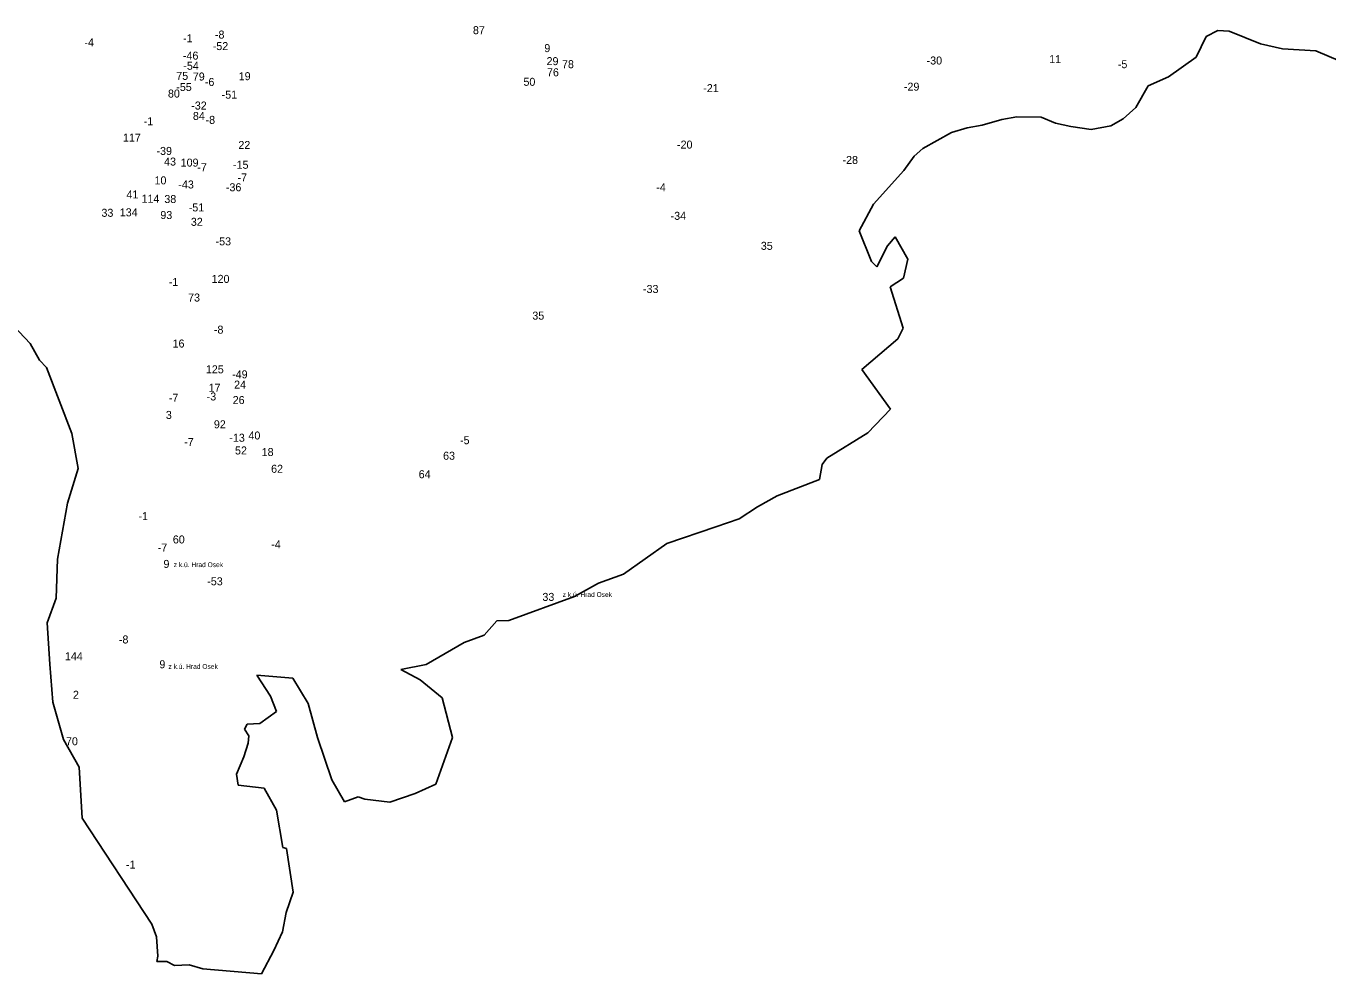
# Model space of a CAD drawing. Extents: x -790709 to -785360, y -974907 to -970918.
# Drawn here: x -788603 to -786976, y -974907 to -973723 of the extents above; entities that cross this region are included whole.
import ezdxf

# ---------------------------------------------------------------- set-up
doc = ezdxf.new("R2010")
doc.units = 0
for name, color, linetype in [('Vrstva 13', 7, 'Continuous'), ('Vrstva 15', 7, 'Continuous'), ('Vrstva 24', 7, 'Continuous'), ('Vrstva 63', 7, 'Continuous')]:
    doc.layers.add(name, color=color, linetype=linetype)

msp = doc.modelspace()

# ---------------------------------------------------------------- linework, layer by layer
at = {"layer": 'Vrstva 13'}
for p, q in [((-787127.9, -973736.1), (-787113.3, -973728.4)), ((-787127.9, -973736.1), (-787113.3, -973728.4)), ((-787127.9, -973736.1), (-787113.3, -973728.4)), ((-787113.3, -973728.4), (-787099.4, -973729.3)), ((-787113.3, -973728.4), (-787099.4, -973729.3)), ((-787113.3, -973728.4), (-787099.4, -973729.3)), ((-787140.6, -973762), (-787127.9, -973736.1)), ((-787140.6, -973762), (-787127.9, -973736.1)), ((-787140.6, -973762), (-787127.9, -973736.1)), ((-787099.4, -973729.3), (-787060.2, -973745.3)), ((-787099.4, -973729.3), (-787060.2, -973745.3)), ((-787099.4, -973729.3), (-787060.2, -973745.3)), ((-787060.2, -973745.3), (-787032.7, -973751.5)), ((-787060.2, -973745.3), (-787032.7, -973751.5)), ((-787060.2, -973745.3), (-787032.7, -973751.5)), ((-787032.7, -973751.5), (-786991, -973754)), ((-787032.7, -973751.5), (-786991, -973754)), ((-787032.7, -973751.5), (-786991, -973754)), ((-786991, -973754), (-786960.6, -973766.9)), ((-786991, -973754), (-786960.6, -973766.9)), ((-786991, -973754), (-786960.6, -973766.9)), ((-787175.1, -973786.5), (-787140.6, -973762)), ((-787175.1, -973786.5), (-787140.6, -973762)), ((-787175.1, -973786.5), (-787140.6, -973762)), ((-787200.5, -973797.6), (-787175.1, -973786.5)), ((-787200.5, -973797.6), (-787175.1, -973786.5)), ((-787200.5, -973797.6), (-787175.1, -973786.5)), ((-787216.1, -973824.8), (-787200.5, -973797.6)), ((-787216.1, -973824.8), (-787200.5, -973797.6)), ((-787216.1, -973824.8), (-787200.5, -973797.6)), ((-787231.7, -973838.8), (-787216.1, -973824.8)), ((-787231.7, -973838.8), (-787216.1, -973824.8)), ((-787231.7, -973838.8), (-787216.1, -973824.8)), ((-787407.8, -973846.9), (-787383.2, -973839.8)), ((-787407.8, -973846.9), (-787383.2, -973839.8)), ((-787407.8, -973846.9), (-787383.2, -973839.8)), ((-787383.2, -973839.8), (-787364.7, -973836.5)), ((-787383.2, -973839.8), (-787364.7, -973836.5)), ((-787383.2, -973839.8), (-787364.7, -973836.5)), ((-787364.7, -973836.5), (-787334.1, -973836.9)), ((-787364.7, -973836.5), (-787334.1, -973836.9)), ((-787364.7, -973836.5), (-787334.1, -973836.9)), ((-787334.1, -973836.9), (-787316.2, -973844.2)), ((-787334.1, -973836.9), (-787316.2, -973844.2)), ((-787334.1, -973836.9), (-787316.2, -973844.2)), ((-787247.1, -973847.5), (-787231.7, -973838.8)), ((-787247.1, -973847.5), (-787231.7, -973838.8)), ((-787247.1, -973847.5), (-787231.7, -973838.8)), ((-787482.1, -973876), (-787446.1, -973856.1)), ((-787482.1, -973876), (-787446.1, -973856.1)), ((-787482.1, -973876), (-787446.1, -973856.1)), ((-787446.1, -973856.1), (-787426.5, -973850)), ((-787446.1, -973856.1), (-787426.5, -973850)), ((-787446.1, -973856.1), (-787426.5, -973850)), ((-787426.5, -973850), (-787407.8, -973846.9)), ((-787426.5, -973850), (-787407.8, -973846.9)), ((-787426.5, -973850), (-787407.8, -973846.9)), ((-787316.2, -973844.2), (-787297.1, -973848.6)), ((-787316.2, -973844.2), (-787297.1, -973848.6)), ((-787316.2, -973844.2), (-787297.1, -973848.6)), ((-787297.1, -973848.6), (-787271.7, -973852.1)), ((-787297.1, -973848.6), (-787271.7, -973852.1)), ((-787297.1, -973848.6), (-787271.7, -973852.1)), ((-787271.7, -973852.1), (-787247.1, -973847.5)), ((-787271.7, -973852.1), (-787247.1, -973847.5)), ((-787271.7, -973852.1), (-787247.1, -973847.5)), ((-787505.8, -973903.5), (-787492.7, -973885.6)), ((-787505.8, -973903.5), (-787492.7, -973885.6)), ((-787505.8, -973903.5), (-787492.7, -973885.6)), ((-787492.7, -973885.6), (-787482.1, -973876)), ((-787492.7, -973885.6), (-787482.1, -973876)), ((-787492.7, -973885.6), (-787482.1, -973876)), ((-787543.7, -973945.4), (-787505.8, -973903.5)), ((-787543.7, -973945.4), (-787505.8, -973903.5)), ((-787543.7, -973945.4), (-787505.8, -973903.5)), ((-787561.8, -973978.7), (-787543.7, -973945.4)), ((-787561.8, -973978.7), (-787543.7, -973945.4)), ((-787561.8, -973978.7), (-787543.7, -973945.4)), ((-787546, -974017), (-787561.8, -973978.7)), ((-787546, -974017), (-787561.8, -973978.7)), ((-787546, -974017), (-787561.8, -973978.7)), ((-787516.5, -973986.2), (-787526.1, -973997.4)), ((-787516.5, -973986.2), (-787526.1, -973997.4)), ((-787516.5, -973986.2), (-787526.1, -973997.4)), ((-787500.7, -974014.1), (-787516.5, -973986.2)), ((-787500.7, -974014.1), (-787516.5, -973986.2)), ((-787500.7, -974014.1), (-787516.5, -973986.2)), ((-787526.1, -973997.4), (-787539.4, -974023.7)), ((-787526.1, -973997.4), (-787539.4, -974023.7)), ((-787526.1, -973997.4), (-787539.4, -974023.7)), ((-787539.4, -974023.7), (-787546, -974017)), ((-787539.4, -974023.7), (-787546, -974017)), ((-787539.4, -974023.7), (-787546, -974017)), ((-787506.1, -974038.2), (-787500.7, -974014.1)), ((-787506.1, -974038.2), (-787500.7, -974014.1)), ((-787506.1, -974038.2), (-787500.7, -974014.1)), ((-788660.2, -974053.6), (-788597.4, -974119.5)), ((-787522.8, -974048.7), (-787506.1, -974038.2)), ((-787522.8, -974048.7), (-787506.1, -974038.2)), ((-787522.8, -974048.7), (-787506.1, -974038.2)), ((-787506.6, -974100.3), (-787522.8, -974048.7)), ((-787506.6, -974100.3), (-787522.8, -974048.7)), ((-787506.6, -974100.3), (-787522.8, -974048.7)), ((-787513.2, -974114), (-787506.6, -974100.3)), ((-787513.2, -974114), (-787506.6, -974100.3)), ((-787513.2, -974114), (-787506.6, -974100.3)), ((-787558.2, -974152.3), (-787513.2, -974114)), ((-787558.2, -974152.3), (-787513.2, -974114)), ((-787558.2, -974152.3), (-787513.2, -974114)), ((-788597.4, -974119.5), (-788585.8, -974140.5)), ((-788585.8, -974140.5), (-788577.2, -974149.6)), ((-788577.2, -974149.6), (-788545.6, -974232.1)), ((-787522.6, -974201.9), (-787558.2, -974152.3)), ((-787522.6, -974201.9), (-787558.2, -974152.3)), ((-787522.6, -974201.9), (-787558.2, -974152.3)), ((-787550.6, -974231.4), (-787522.6, -974201.9)), ((-787550.6, -974231.4), (-787522.6, -974201.9)), ((-787550.6, -974231.4), (-787522.6, -974201.9)), ((-788545.6, -974232.1), (-788537.5, -974276)), ((-787601.8, -974263), (-787550.6, -974231.4)), ((-787601.8, -974263), (-787550.6, -974231.4)), ((-787601.8, -974263), (-787550.6, -974231.4)), ((-787607.8, -974270.8), (-787601.8, -974263)), ((-787607.8, -974270.8), (-787601.8, -974263)), ((-787607.8, -974270.8), (-787601.8, -974263)), ((-788537.5, -974276), (-788550.7, -974319.1)), ((-787611.1, -974289.5), (-787607.8, -974270.8)), ((-787611.1, -974289.5), (-787607.8, -974270.8)), ((-787611.1, -974289.5), (-787607.8, -974270.8)), ((-787664.2, -974310.2), (-787611.1, -974289.5)), ((-787664.2, -974310.2), (-787611.1, -974289.5)), ((-787664.2, -974310.2), (-787611.1, -974289.5)), ((-787688.7, -974323.7), (-787664.2, -974310.2)), ((-787688.7, -974323.7), (-787664.2, -974310.2)), ((-787688.7, -974323.7), (-787664.2, -974310.2)), ((-788550.7, -974319.1), (-788563.5, -974389.2)), ((-787711.6, -974338.6), (-787688.7, -974323.7)), ((-787711.6, -974338.6), (-787688.7, -974323.7)), ((-787711.6, -974338.6), (-787688.7, -974323.7)), ((-787740.6, -974348.6), (-787711.6, -974338.6)), ((-787740.6, -974348.6), (-787711.6, -974338.6)), ((-787740.6, -974348.6), (-787711.6, -974338.6)), ((-787802, -974369.7), (-787740.6, -974348.6)), ((-787802, -974369.7), (-787740.6, -974348.6)), ((-787802, -974369.7), (-787740.6, -974348.6)), ((-787855.9, -974407.8), (-787802, -974369.7)), ((-787855.9, -974407.8), (-787802, -974369.7)), ((-787855.9, -974407.8), (-787802, -974369.7)), ((-788563.5, -974389.2), (-788565, -974437.7)), ((-787887.3, -974419.3), (-787855.9, -974407.8)), ((-787887.3, -974419.3), (-787855.9, -974407.8)), ((-787887.3, -974419.3), (-787855.9, -974407.8)), ((-787917.1, -974435.9), (-787887.3, -974419.3)), ((-787917.1, -974435.9), (-787887.3, -974419.3)), ((-787917.1, -974435.9), (-787887.3, -974419.3)), ((-788565, -974437.7), (-788576.2, -974468.8)), ((-787999.3, -974465.7), (-787917.1, -974435.9)), ((-787999.3, -974465.7), (-787917.1, -974435.9)), ((-787999.3, -974465.7), (-787917.1, -974435.9)), ((-788576.2, -974468.8), (-788572.8, -974520.5)), ((-788030.1, -974484.2), (-788014.5, -974466.1)), ((-788030.1, -974484.2), (-788014.5, -974466.1)), ((-788030.1, -974484.2), (-788014.5, -974466.1)), ((-788014.5, -974466.1), (-787999.3, -974465.7)), ((-788014.5, -974466.1), (-787999.3, -974465.7)), ((-788014.5, -974466.1), (-787999.3, -974465.7)), ((-788102.7, -974520.9), (-788055.3, -974493.4)), ((-788102.7, -974520.9), (-788055.3, -974493.4)), ((-788102.7, -974520.9), (-788055.3, -974493.4)), ((-788055.3, -974493.4), (-788030.1, -974484.2)), ((-788055.3, -974493.4), (-788030.1, -974484.2)), ((-788055.3, -974493.4), (-788030.1, -974484.2)), ((-788572.8, -974520.5), (-788569.1, -974568)), ((-788134.2, -974527.1), (-788102.7, -974520.9)), ((-788134.2, -974527.1), (-788102.7, -974520.9)), ((-788134.2, -974527.1), (-788102.7, -974520.9)), ((-788297.1, -974560.4), (-788314.2, -974534)), ((-788314.2, -974534), (-788269.2, -974537.9)), ((-788297.1, -974560.4), (-788314.2, -974534)), ((-788314.2, -974534), (-788269.2, -974537.9)), ((-788297.1, -974560.4), (-788314.2, -974534)), ((-788314.2, -974534), (-788269.2, -974537.9)), ((-788269.2, -974537.9), (-788250.1, -974569.4)), ((-788269.2, -974537.9), (-788250.1, -974569.4)), ((-788269.2, -974537.9), (-788250.1, -974569.4)), ((-788110.2, -974539.8), (-788134.2, -974527.1)), ((-788110.2, -974539.8), (-788134.2, -974527.1)), ((-788110.2, -974539.8), (-788134.2, -974527.1)), ((-788082.5, -974562.3), (-788110.2, -974539.8)), ((-788082.5, -974562.3), (-788110.2, -974539.8)), ((-788082.5, -974562.3), (-788110.2, -974539.8)), ((-788569.1, -974568), (-788555.7, -974614.7)), ((-788289.8, -974579.4), (-788297.1, -974560.4)), ((-788289.8, -974579.4), (-788297.1, -974560.4)), ((-788289.8, -974579.4), (-788297.1, -974560.4)), ((-788250.1, -974569.4), (-788238.4, -974611.8)), ((-788250.1, -974569.4), (-788238.4, -974611.8)), ((-788250.1, -974569.4), (-788238.4, -974611.8)), ((-788069.8, -974612), (-788082.5, -974562.3)), ((-788069.8, -974612), (-788082.5, -974562.3)), ((-788069.8, -974612), (-788082.5, -974562.3)), ((-788310.6, -974594.4), (-788289.8, -974579.4)), ((-788310.6, -974594.4), (-788289.8, -974579.4)), ((-788310.6, -974594.4), (-788289.8, -974579.4)), ((-788329.6, -974601.4), (-788326.3, -974595.2)), ((-788329.6, -974601.4), (-788326.3, -974595.2)), ((-788329.6, -974601.4), (-788326.3, -974595.2)), ((-788324.4, -974610), (-788329.6, -974601.4)), ((-788324.4, -974610), (-788329.6, -974601.4)), ((-788324.4, -974610), (-788329.6, -974601.4)), ((-788326.3, -974595.2), (-788310.6, -974594.4)), ((-788326.3, -974595.2), (-788310.6, -974594.4)), ((-788326.3, -974595.2), (-788310.6, -974594.4)), ((-788555.7, -974614.7), (-788536.2, -974648.9)), ((-788330.6, -974636), (-788325.2, -974618.9)), ((-788330.6, -974636), (-788325.2, -974618.9)), ((-788330.6, -974636), (-788325.2, -974618.9)), ((-788325.2, -974618.9), (-788324.4, -974610)), ((-788325.2, -974618.9), (-788324.4, -974610)), ((-788325.2, -974618.9), (-788324.4, -974610)), ((-788238.4, -974611.8), (-788220.7, -974665.1)), ((-788238.4, -974611.8), (-788220.7, -974665.1)), ((-788238.4, -974611.8), (-788220.7, -974665.1)), ((-788090.7, -974670.3), (-788069.8, -974612)), ((-788090.7, -974670.3), (-788069.8, -974612)), ((-788090.7, -974670.3), (-788069.8, -974612)), ((-788339.8, -974657.9), (-788330.6, -974636)), ((-788339.8, -974657.9), (-788330.6, -974636)), ((-788339.8, -974657.9), (-788330.6, -974636)), ((-788536.2, -974648.9), (-788532.3, -974712.8)), ((-788337.7, -974671.4), (-788339.8, -974657.9)), ((-788337.7, -974671.4), (-788339.8, -974657.9)), ((-788337.7, -974671.4), (-788339.8, -974657.9)), ((-788305, -974675.3), (-788337.7, -974671.4)), ((-788305, -974675.3), (-788337.7, -974671.4)), ((-788305, -974675.3), (-788337.7, -974671.4)), ((-788220.7, -974665.1), (-788204.7, -974692.4)), ((-788220.7, -974665.1), (-788204.7, -974692.4)), ((-788220.7, -974665.1), (-788204.7, -974692.4)), ((-788116.3, -974682), (-788090.7, -974670.3)), ((-788116.3, -974682), (-788090.7, -974670.3)), ((-788116.3, -974682), (-788090.7, -974670.3)), ((-788289.6, -974702.8), (-788305, -974675.3)), ((-788289.6, -974702.8), (-788305, -974675.3)), ((-788289.6, -974702.8), (-788305, -974675.3)), ((-788204.7, -974692.4), (-788187.8, -974686.2)), ((-788204.7, -974692.4), (-788187.8, -974686.2)), ((-788204.7, -974692.4), (-788187.8, -974686.2)), ((-788187.8, -974686.2), (-788179.3, -974689.1)), ((-788187.8, -974686.2), (-788179.3, -974689.1)), ((-788187.8, -974686.2), (-788179.3, -974689.1)), ((-788148.1, -974692.6), (-788116.3, -974682)), ((-788148.1, -974692.6), (-788116.3, -974682)), ((-788148.1, -974692.6), (-788116.3, -974682)), ((-788281.7, -974749.5), (-788289.6, -974702.8)), ((-788281.7, -974749.5), (-788289.6, -974702.8)), ((-788281.7, -974749.5), (-788289.6, -974702.8)), ((-788179.3, -974689.1), (-788148.1, -974692.6)), ((-788179.3, -974689.1), (-788148.1, -974692.6)), ((-788179.3, -974689.1), (-788148.1, -974692.6)), ((-788532.3, -974712.8), (-788445.4, -974845.1)), ((-788277.1, -974750.7), (-788281.7, -974749.5)), ((-788277.1, -974750.7), (-788281.7, -974749.5)), ((-788277.1, -974750.7), (-788281.7, -974749.5)), ((-788269, -974805.3), (-788277.1, -974750.7)), ((-788269, -974805.3), (-788277.1, -974750.7)), ((-788269, -974805.3), (-788277.1, -974750.7)), ((-788277.6, -974830.7), (-788269, -974805.3)), ((-788277.6, -974830.7), (-788269, -974805.3)), ((-788277.6, -974830.7), (-788269, -974805.3)), ((-788282.3, -974854.8), (-788277.6, -974830.7)), ((-788282.3, -974854.8), (-788277.6, -974830.7)), ((-788282.3, -974854.8), (-788277.6, -974830.7)), ((-788445.4, -974845.1), (-788439.4, -974861)), ((-788439.4, -974861), (-788438.1, -974885.3)), ((-788292.8, -974878.3), (-788282.3, -974854.8)), ((-788292.8, -974878.3), (-788282.3, -974854.8)), ((-788292.8, -974878.3), (-788282.3, -974854.8)), ((-788308.2, -974907.5), (-788292.8, -974878.3)), ((-788308.2, -974907.5), (-788292.8, -974878.3)), ((-788308.2, -974907.5), (-788292.8, -974878.3)), ((-788438.1, -974885.3), (-788439, -974892.1)), ((-788439, -974892.1), (-788426.5, -974892.1)), ((-788439, -974892.1), (-788426.5, -974892.1)), ((-788439, -974892.1), (-788426.5, -974892.1)), ((-788426.5, -974892.1), (-788417.3, -974897.1)), ((-788426.5, -974892.1), (-788417.3, -974897.1)), ((-788426.5, -974892.1), (-788417.3, -974897.1)), ((-788417.3, -974897.1), (-788398.6, -974896.2)), ((-788417.3, -974897.1), (-788398.6, -974896.2)), ((-788417.3, -974897.1), (-788398.6, -974896.2)), ((-788398.6, -974896.2), (-788381.9, -974901.2)), ((-788398.6, -974896.2), (-788381.9, -974901.2)), ((-788398.6, -974896.2), (-788381.9, -974901.2)), ((-788381.9, -974901.2), (-788308.2, -974907.5)), ((-788381.9, -974901.2), (-788308.2, -974907.5)), ((-788381.9, -974901.2), (-788308.2, -974907.5))]:
    msp.add_line(p, q, dxfattribs=at)

# ---------------------------------------------------------------- texts
at = {"layer": 'Vrstva 15'}
for s, p in [('-8', (-788366.6, -973738.6)), ('-4', (-788529.7, -973748.4)), ('-1', (-788406.4, -973743.2)), ('-52', (-788369.3, -973753)), ('-46', (-788406.6, -973764.9)), ('-30', (-787477.3, -973771)), ('-54', (-788406.1, -973777.6)), ('-5', (-787238.4, -973775.6)), ('-6', (-788379.2, -973797.8)), ('-29', (-787505.7, -973803.7)), ('-55', (-788414.9, -973804.1)), ('-51', (-788358.2, -973813.7)), ('-21', (-787756.4, -973805.5)), ('-32', (-788396.2, -973827.3)), ('-1', (-788455.6, -973846.9)), ('-8', (-788378.3, -973845.2)), ('-39', (-788439.6, -973884)), ('-20', (-787789.2, -973876.1)), ('-15', (-788344, -973901.3)), ('-28', (-787582.4, -973895.3)), ('-7', (-788388.6, -973904.4)), ('-7', (-788338.4, -973917.2)), ('-43', (-788412.3, -973925.9)), ('-36', (-788352.9, -973929.4)), ('-4', (-787815.1, -973929.4)), ('-51', (-788399.3, -973954.6)), ('-34', (-787797.2, -973965.1)), ('-53', (-788365.8, -973997)), ('-1', (-788424.3, -974047.8)), ('-33', (-787831.7, -974056.5)), ('-8', (-788367.9, -974107.3)), ('-49', (-788345.1, -974163.2)), ('-7', (-788424.2, -974192.5)), ('-3', (-788376.9, -974190.8)), ('-13', (-788348.6, -974242.4)), ('-7', (-788405, -974247.7)), ('-5', (-788060.3, -974245.5)), ('-1', (-788462.1, -974340.3)), ('-7', (-788438.1, -974379.7)), ('-4', (-788296.2, -974375.6)), ('-53', (-788376.2, -974421.8)), ('-8', (-788486.6, -974494.5)), ('-1', (-788477.7, -974775.9))]:
    msp.add_text(s, height=10, dxfattribs=at).set_placement(p)
at = {"layer": 'Vrstva 24'}
for s, p in [('92', (-788367.9, -974225.6)), ('33 ', (-787957.4, -974441.3))]:
    msp.add_text(s, height=10, dxfattribs=at).set_placement(p)
at = {"layer": 'Vrstva 63'}
for s, height, p in [('87', 10, (-788044.2, -973733.1)), ('9', 10, (-787955, -973755.5)), ('11', 10, (-787324.2, -973769.3)), ('29', 10, (-787952.2, -973771.8)), ('76', 10, (-787951.7, -973785.7)), ('78', 10, (-787932.9, -973775.6)), ('75', 10, (-788414.9, -973790.2)), ('79', 10, (-788394.2, -973791)), ('19', 10, (-788336.9, -973790.6)), ('50', 10, (-787981.1, -973797.6)), ('80', 10, (-788425.3, -973812.3)), ('84', 10, (-788394.1, -973840.3)), ('117', 10, (-788481.5, -973867.4)), ('22', 10, (-788337.3, -973876.6)), ('43', 10, (-788430.1, -973897.3)), ('109', 10, (-788409.4, -973898.6)), ('10', 10, (-788442.1, -973920.8)), ('41', 10, (-788477.1, -973938.4)), ('114', 10, (-788458.3, -973943.7)), ('38', 10, (-788429.8, -973944.1)), ('33', 10, (-788508.4, -973961.3)), ('134', 10, (-788485.5, -973960.7)), ('93', 10, (-788434.8, -973964.1)), ('32', 10, (-788396.7, -973972.6)), ('35', 10, (-787684.5, -974002.6)), ('120', 10, (-788370.7, -974043.9)), ('73', 10, (-788400.1, -974067.2)), ('35', 10, (-787970, -974089.8)), ('16', 10, (-788419.5, -974124.7)), ('125', 10, (-788377.9, -974156.9)), ('24', 10, (-788342.6, -974176)), ('17', 10, (-788374.5, -974179.9)), ('26', 10, (-788344.4, -974195.3)), ('3', 10, (-788427.9, -974213.9)), ('40', 10, (-788324.7, -974239.6)), ('52', 10, (-788341.5, -974258.3)), ('18', 10, (-788308.2, -974260.3)), ('63', 10, (-788081.5, -974264.9)), ('62', 10, (-788296.4, -974281.2)), ('64', 10, (-788112, -974288)), ('60', 10, (-788419.2, -974369.5)), ('9', 10, (-788430.9, -974400.1)), ('z k.ú. Hrad Osek', 6, (-788418.1, -974399.1)), ('z k.ú. Hrad Osek', 6, (-787932.1, -974436.3)), ('144', 10, (-788554, -974515.4)), ('9', 10, (-788436, -974525.5)), ('z k.ú. Hrad Osek', 6, (-788424.7, -974526.2)), ('2', 10, (-788544, -974563.6)), ('70', 10, (-788552.7, -974621.7))]:
    msp.add_text(s, height=height, dxfattribs=at).set_placement(p)

doc.saveas('drawing.dxf')
